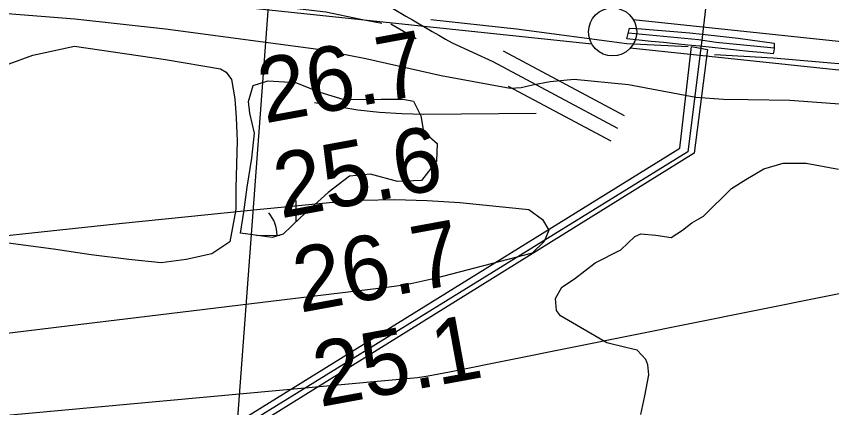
# Model space of a CAD drawing. Extents: x 3355677 to 3393573, y 612928 to 638357.
# Drawn here: x 3363913 to 3364759, y 624714 to 625120 of the extents above; entities that cross this region are included whole.
import ezdxf

# ---------------------------------------------------------------- set-up
doc = ezdxf.new("R2010")
doc.units = 0
for name, color, linetype in [('V-BRDG-OTLN', 7, 'Continuous'), ('V-CHAN-DOCK', 7, 'Continuous'), ('V-FLOD-BASE', 7, 'Continuous'), ('V-LEVE-TOET', 7, 'Continuous'), ('V-RIVR-RANG', 7, 'Continuous'), ('V-ROAD-CNTR', 7, 'Continuous'), ('V-SITE-VEGE', 7, 'Continuous'), ('V-SURV-LINE', 7, 'Continuous'), ('V-TOPO-MAJR', 7, 'Continuous'), ('V-TOPO-MINR', 7, 'Continuous'), ('V-UTIL-LINE', 7, 'Continuous'), ('V-WETL-SWMP', 7, 'Continuous')]:
    doc.layers.add(name, color=color, linetype=linetype)

msp = doc.modelspace()

# ---------------------------------------------------------------- linework, layer by layer
at = {"layer": 'V-BRDG-OTLN'}
msp.add_lwpolyline([(3364549.35, 625107.7), (3364561.88, 625106.9), (3364574.42, 625106.01), (3364586.97, 625105.02), (3364599.52, 625103.94), (3364612.07, 625102.77), (3364624.62, 625101.51), (3364637.15, 625100.16), (3364649.67, 625098.71), (3364662.18, 625097.18), (3364674.66, 625095.56), (3364687.12, 625093.85), (3364699.55, 625092.05), (3364699.71, 625089.24), (3364699.58, 625086.43), (3364699.16, 625083.64), (3364698.47, 625080.91), (3364685.84, 625082.24), (3364673.2, 625083.57), (3364660.54, 625084.88), (3364647.88, 625086.2), (3364635.21, 625087.51), (3364622.53, 625088.81), (3364609.85, 625090.11), (3364597.18, 625091.4), (3364584.51, 625092.68), (3364571.85, 625093.96), (3364559.21, 625095.22), (3364546.58, 625096.48)], close=True, dxfattribs=at)
msp.add_lwpolyline([(3364548.24, 625102.97), (3364621.03, 625095.83), (3364639.18, 625093.09), (3364699.53, 625087.33)], dxfattribs=at)
at = {"layer": 'V-CHAN-DOCK'}
for points in [[(3363900.02, 624313.37), (3363900.53, 624332.73), (3363921.38, 624331.56), (3363927.14, 624461.53), (3363927.68, 624487.89), (3363929.91, 624568.19), (3363951.93, 624582.35), (3363943.93, 624594.59), (3363980.03, 624617.37), (3363990.49, 624604.53), (3364601.76, 624983.21), (3364613.72, 625088.68), (3364630.28, 625085.66)], [(3364630.28, 625085.66), (3364616.49, 624977.74), (3364013.78, 624603.36), (3364012.27, 624487.51), (3364011.11, 624463.6), (3364010.27, 624327.53), (3364058.08, 624327.66)]]:
    msp.add_lwpolyline(points, dxfattribs=at)
at = {"layer": 'V-FLOD-BASE'}
for points in [[(3362000.77, 625039.28), (3362153.17, 625064.19), (3362360.81, 625092.75), (3362504.83, 625113.44), (3362708.54, 625144.08), (3362865.14, 625169.7), (3362985.38, 625188.22), (3363125.9, 625207.51), (3363202.82, 625212.62), (3363267.86, 625214.9), (3363381.16, 625216.61), (3363462.31, 625209.15), (3363630.2, 625192.84), (3363736.55, 625179.85), (3363858.98, 625167.6), (3363988.4, 625154.68), (3364110.14, 625139.64), (3364233.97, 625124.6), (3364270.36, 625117.01), (3364292.06, 625112.87)], [(3364343.1, 625116.51), (3364431.95, 625106.97), (3364546.69, 625091.91), (3364610.35, 625088.59)], [(3364637.65, 625080.27), (3364698.5, 625076.95), (3364798.54, 625068.14), (3364996.54, 625044.22), (3365182.63, 625025.86), (3365229.51, 625019.7), (3365289.67, 625012.87), (3365372.22, 625005.41), (3365461.07, 624996.57), (3365545.02, 624986.31), (3365599.61, 624976.68), (3365717.2, 624943.44), (3365806.61, 624919.63)]]:
    msp.add_lwpolyline(points, dxfattribs=at)
at = {"layer": 'V-LEVE-TOET'}
msp.add_lwpolyline([(3363811.37, 625130.12), (3363973.29, 625117.32), (3364067.52, 625107.12), (3364225.96, 625085.94), (3364275.54, 625076.31), (3364353.73, 625058.39), (3364421.45, 625046.02), (3364425.64, 625045.33), (3364436.8, 625046.06), (3364448.65, 625048.88), (3364466.79, 625052.42), (3364491.9, 625054.59), (3364548.43, 625049.17), (3364618.25, 625036.1), (3364646.86, 625034.09), (3364672.68, 625033.46), (3364715.94, 625032.89), (3364805.27, 625026.16)], dxfattribs=at)
at = {"layer": 'V-RIVR-RANG'}
msp.add_line((3364175.06, 625143.15), (3364077.96, 623846.77), dxfattribs=at)
at = {"layer": 'V-ROAD-CNTR'}
for points in [[(3364301.39, 625112.06), (3364327.78, 625096.76)], [(3364365.15, 625092.43), (3364407.31, 625073.04), (3364536.89, 625003.8)], [(3364418.14, 625084.26), (3364543.96, 625017.03)], [(3364423.25, 625047.51), (3364529.81, 624990.57)]]:
    msp.add_lwpolyline(points, dxfattribs=at)
msp.add_arc((3367296.94, 630216.07), 5903.14, 237.755521, 240.221516, dxfattribs=at)
at = {"layer": 'V-SITE-VEGE'}
for points in [[(3363905.13, 625070.52), (3363929.58, 625079.68), (3363972.92, 625088.89), (3364067.38, 625075.17), (3364124.75, 625065.54), (3364130.36, 625062.06), (3364135.98, 625054.38), (3364139.53, 625034.11), (3364140.98, 625014.53), (3364141.75, 624990.76), (3364140.49, 624941.79), (3364140.55, 624919.41), (3364134.35, 624885.83), (3364115.5, 624873.18), (3364088.94, 624867.52), (3364063.08, 624863.94), (3364029.5, 624867.34), (3363990.32, 624872.13), (3363951.13, 624878.32), (3363904.25, 624884.48)], [(3364561, 624706.35), (3364565.14, 624725.92), (3364569.27, 624747.59), (3364568.54, 624758.06), (3364566.43, 624763.65), (3364557.32, 624773.4), (3364545.44, 624776.16), (3364525.87, 624780.99), (3364477.59, 624808.8), (3364473.38, 624814.37), (3364472.65, 624826.94), (3364478.91, 624838.83), (3364492.15, 624847.25), (3364513.76, 624864.08), (3364540.26, 624877.42), (3364554.89, 624891.43), (3364561.17, 624894.25), (3364576.54, 624892.89), (3364592.62, 624890.14), (3364604.47, 624897.86), (3364614.23, 624905.57), (3364626.08, 624912.59), (3364655.33, 624941.31), (3364669.98, 624950.43), (3364688.81, 624961.66), (3364709.04, 624967.31), (3364732.79, 624967.37), (3364766.34, 624961.18)]]:
    msp.add_lwpolyline(points, dxfattribs=at)
at = {"layer": 'V-SURV-LINE'}
for points in [[(3364510.34, 625091.01), (3363406, 625207.71)], [(3364553.24, 625116.65), (3365537.69, 625012.88)], [(3365534.53, 624983.05), (3364550.08, 625086.82)]]:
    msp.add_lwpolyline(points, dxfattribs=at)
msp.add_circle((3364531.79, 625103.83), 25, dxfattribs=at)
at = {"layer": 'V-TOPO-MAJR'}
for points in [[(3364452.57, 625019.04), (3364335.69, 625018.16), (3364312.75, 625018.65), (3364289.88, 625020), (3364267.12, 625022.66), (3364244.44, 625026.2), (3364222.32, 625030.29)], [(3364305.43, 624929.91), (3364339.26, 624928.87), (3364373.08, 624926.5), (3364444.94, 624919.3), (3364459.12, 624908.97), (3364465.69, 624898.06), (3364460.85, 624886.27), (3364448.41, 624873.91), (3364347.13, 624847.8), (3364334.78, 624844.87), (3364322.38, 624842.28), (3364309.88, 624840.18), (3364297.31, 624838.4), (3364179.71, 624824.14), (3364108.3, 624815.49), (3364036.88, 624806.85), (3363965.47, 624798.23), (3363894.05, 624789.63), (3363532.42, 624746.08), (3363507.73, 624743.05), (3363483.05, 624739.92), (3363458.39, 624736.67), (3363433.74, 624733.33), (3362756.48, 624639.82)], [(3363294.89, 624833.79), (3363421.64, 624841.93), (3363443.68, 624843.5), (3363465.71, 624845.26), (3363487.71, 624847.32), (3363509.69, 624849.57), (3363876.65, 624889.68), (3363948.07, 624897.37), (3364019.51, 624904.89), (3364090.97, 624912.17), (3364162.45, 624919.28), (3364237.76, 624926.65), (3364271.6, 624928.95), (3364305.43, 624929.91)]]:
    msp.add_lwpolyline(points, dxfattribs=at)
at = {"layer": 'V-TOPO-MINR'}
msp.add_lwpolyline([(3364839.52, 624846.51), (3364758.54, 624830.2), (3364677.56, 624813.91), (3364362.25, 624750.51), (3364351.25, 624748.42), (3364340.23, 624746.47), (3364329.17, 624744.75), (3363517.74, 624670.07), (3363506.3, 624669.25), (3363494.86, 624668.43), (3363483.42, 624667.62), (3362725.46, 624585.06)], dxfattribs=at)
at = {"layer": 'V-UTIL-LINE'}
msp.add_lwpolyline([(3364894.64, 626267.88), (3364879.95, 626269.23), (3364754.81, 625756.93), (3364652.41, 625360.78), (3364647.66, 625309.71), (3364648.38, 625300.62), (3364624.43, 625095.31), (3364610.07, 624979.17), (3364008.94, 624608.2)], dxfattribs=at)
at = {"layer": 'V-WETL-SWMP'}
for p, q in [((3364203.24, 624906.88), (3364203.19, 624928.61)), ((3364162.24, 624892.51), (3364186.08, 624892.57))]:
    msp.add_line(p, q, dxfattribs=at)
msp.add_lwpolyline([(3364178.4, 624890.15), (3364145.52, 624894.95), (3364148.95, 624916.64), (3364152.38, 624942.53), (3364157.19, 624972.61), (3364159.91, 624998.5), (3364154.96, 625019.47), (3364153.53, 625031.35), (3364158.37, 625048.15), (3364173.75, 625053.09), (3364202.43, 625051.07), (3364227.63, 625041.35), (3364252.83, 625033.73), (3364291.3, 625033.84), (3364314.38, 625033.9), (3364324.88, 625031.84), (3364332.61, 625016.47), (3364335.46, 625000.39), (3364349.48, 624987.84), (3364348.83, 624969.66), (3364333.5, 624949.33), (3364308.33, 624948.56), (3364280.33, 624956.18), (3364258.65, 624954.02), (3364236.32, 624937.17), (3364207.72, 624911.21), (3364189.58, 624893.67)], close=True, dxfattribs=at)
msp.add_arc((3364148.04, 624892.94), 35.25, 359.37818, 40.92184, dxfattribs=at)

# ---------------------------------------------------------------- texts
at = {"layer": 'V-RIVR-RANG'}
for s, p in [('26.7', (3364170.56, 625008.66)), ('25.6', (3364187.06, 624910.01)), ('26.7', (3364207.18, 624812.04)), ('25.1', (3364227.83, 624714.16))]:
    msp.add_text(s, height=67, rotation=10.40833, dxfattribs=at).set_placement(p)

doc.saveas('drawing.dxf')
